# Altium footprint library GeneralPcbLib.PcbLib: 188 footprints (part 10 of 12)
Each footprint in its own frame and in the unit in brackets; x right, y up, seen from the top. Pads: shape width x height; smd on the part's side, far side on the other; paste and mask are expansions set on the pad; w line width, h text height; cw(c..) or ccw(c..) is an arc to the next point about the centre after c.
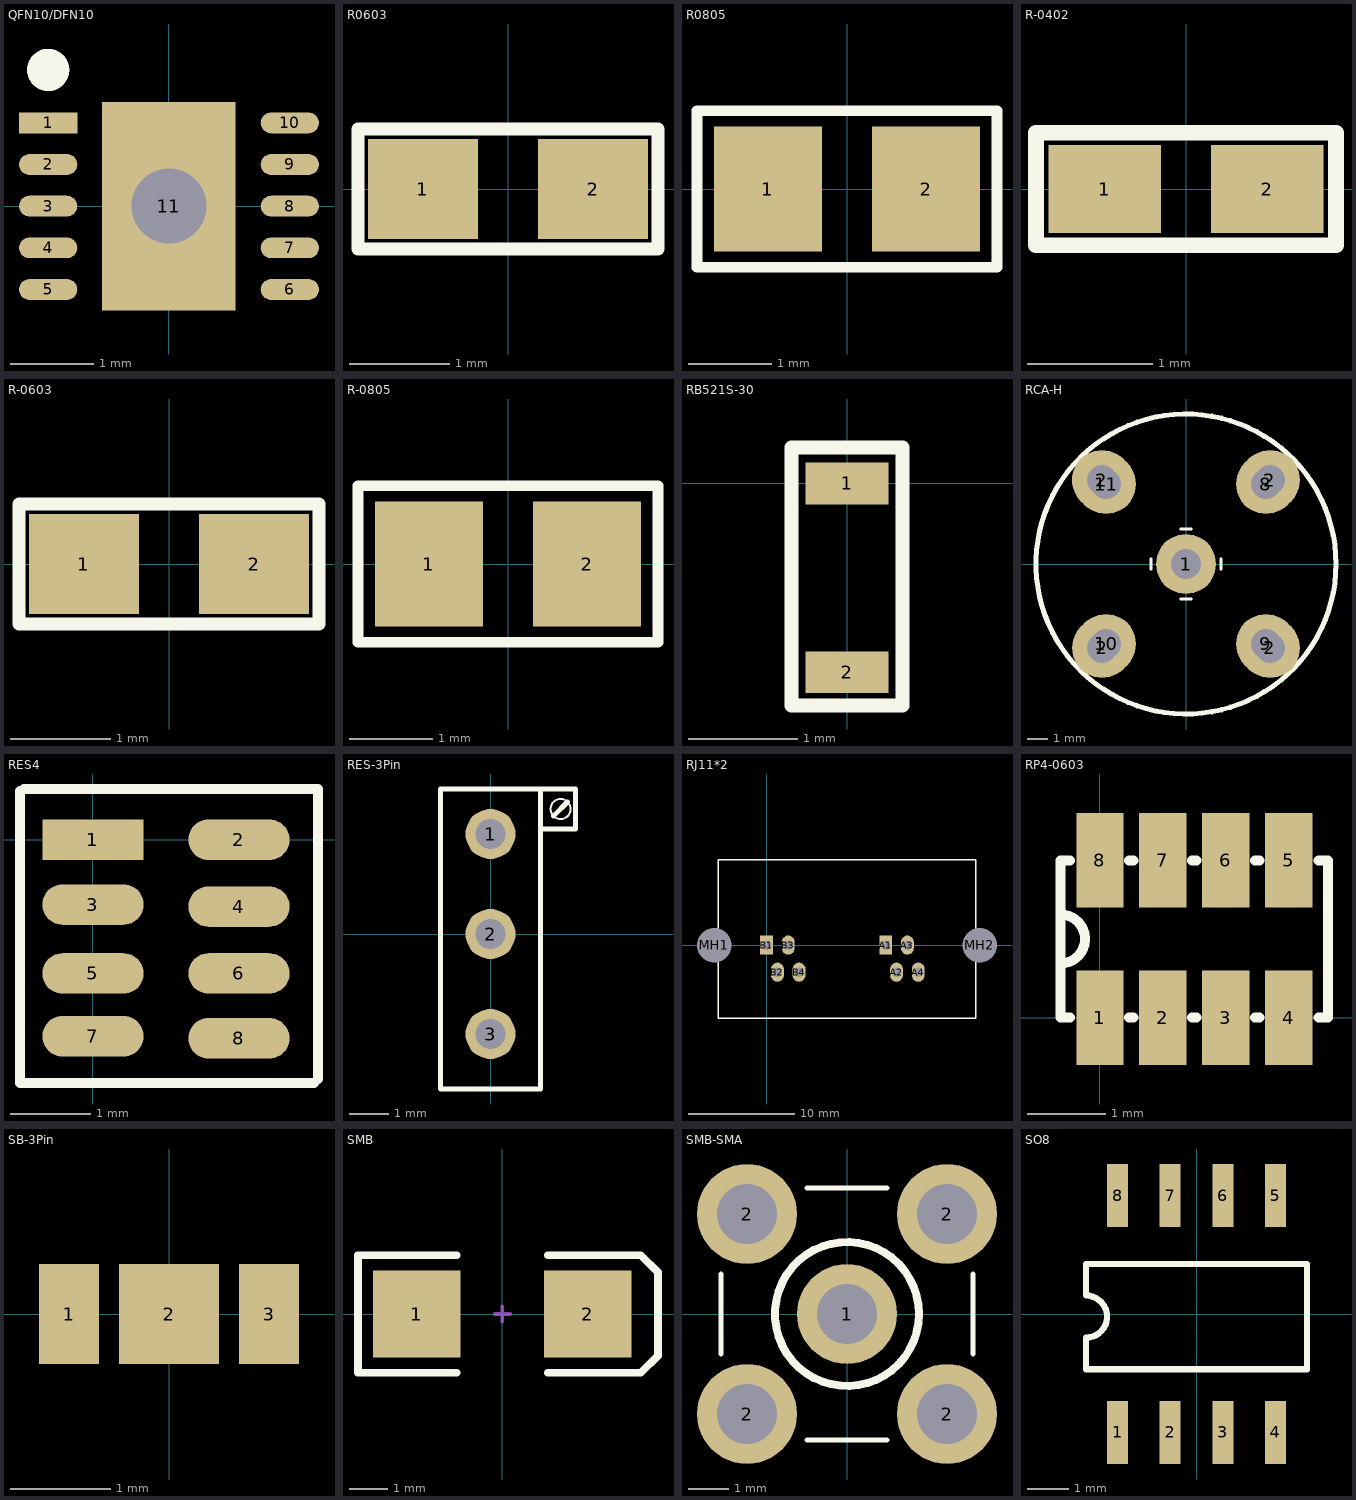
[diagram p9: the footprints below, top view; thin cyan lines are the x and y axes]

## QFN10/DFN10 [mm] "LT3471"
pads (11):
  rect 0.7x0.25 smd: 1(-1.448,1)
  oval 0.7x0.25 smd: 2(-1.448,0.5) 3(-1.448,0) 4(-1.448,-0.5) 5(-1.448,-1) 6(1.452,-1) 7(1.452,-0.5) 8(1.452,0) 9(1.452,0.5) 10(1.452,1)
  rect 1.6x2.5 hole 0.9: 11(0,0)
Top Overlay:
  circle w0.254: c-1.448,1.635 r0.127

## R0603 [mm]
pads (2):
  rect 1.1x1 smd: 1(-0.85,0) 2(0.85,0)
Top Overlay:
  lines w0.127: -1.5,-0.6 1.5,-0.6 1.5,0.6 -1.5,0.6 -1.5,-0.6

## R0805 [mm]
pads (2):
  rect 1.3x1.5 smd: 1(-0.95,0) 2(0.95,0)
Top Overlay:
  lines w0.127: -1.803,-0.94 -1.803,0.94 1.803,0.94 1.803,-0.94 -1.803,-0.94

## R-0402 [mm]
pads (2):
  rect 0.9x0.7 smd: 1(-0.65,0) 2(0.65,0)
Top Overlay:
  lines w0.127: -1.2,-0.45 -1.2,0.45 1.2,0.45 1.2,-0.45 -1.2,-0.45
3D body: height 0.3, standoff 0, extent 0.508,-0.254 1.016,0.254
3D body: height 0.3, standoff 0, extent -1.016,-0.254 -0.508,0.254

## R-0603 [mm]
height 0.5
pads (2):
  rect 1.1x1 smd: 1(-0.85,0) 2(0.85,0)
Top Overlay:
  lines w0.127: -1.5,-0.6 1.5,-0.6 1.5,0.6 -1.5,0.6 -1.5,-0.6
3D body: height 0.5, standoff 0, extent -1.35,-0.45 1.35,0.45

## R-0805 [mm]
pads (2):
  rect 1.3x1.5 smd: 1(-0.95,0) 2(0.95,0)
Top Overlay:
  lines w0.127: -1.803,-0.94 1.803,-0.94 1.803,0.94 -1.803,0.94 -1.803,-0.94

## RB521S-30 [mil]
pads (3):
  round 10 on Top Overlay: 0(-15,20)
  rect 30x15 smd: 1(0,0) 2(0,-68)
Top Overlay:
  lines w5: -20,-80 -20,13 20,13 20,-80 -20,-80

## RCA-H [mm] "立式RCA"
pads (9):
  round 3 hole 1.5: 1(0,0) 2(-4.2,4.2) 2(-4.2,-4.2) 2(4.2,-4.2) 2(4.2,4.2) 8(4,4) 9(4,-4) 10(-4,-4) 11(-4,4)
Top Overlay:
  circle w0.254: c0,0 r7.5
  lines w0.127: -1.75,-0.27 -1.75,0.27 ; -0.27,-1.75 0.27,-1.75 ; -0.27,1.75 0.27,1.75 ; 1.75,-0.27 1.75,0.27

## RES4 [mil] "RES4-0603"
pads (8):
  rect 50x20 smd: 1(0,0)
  oval 50x20 smd: 2(72,0) 3(0,-32) 4(72,-33) 5(0,-66) 6(72,-66) 7(0,-97) 8(72,-98)
Top Overlay:
  lines w5: -36,24 -36,-96 -36,-105.62 -36,-120 109,-120 ; -34,25 111,25 111,12.38 111,-107.62 111,-118

## RES-3Pin [mil] "可调电位器"
height 393.7
pads (3):
  round 50 hole 30: 1(0,100) 2(0,0) 3(0,-100)
Top Overlay:
  circle w2: c70,125 r10
  lines w5: 50,105 85,105 85,145 50,145 ; 63.16,118.16 77,132 ; 50,145 50,-155 -50,-155 -50,145 50,145

## RJ11*2 [mm] "2位RJ11接口座"
height 10
pads (10):
  rect 1.2x1.8 hole 0.9: A1(11.176,0) B1(0,0)
  oval 1.2x1.8 hole 0.9: A2(12.192,-2.54) A3(13.208,0) A4(14.224,-2.54) B2(1.016,-2.54) B3(2.032,0) B4(3.048,-2.54)
  round 2.95 hole 3.25 unplated: MH1(-4.902,0) MH2(19.99,0)
Top Overlay:
  lines w0.127: -4.521,-6.858 -4.521,8.001 19.609,8.001 19.609,-6.858 -4.521,-6.858

## RP4-0603 [mm]
pads (8):
  rect 0.6x1.2 smd: 1(0,0) 2(0.8,0) 3(1.6,0) 4(2.4,0) 5(2.4,2) 6(1.6,2) 7(0.8,2) 8(0,2)
Top Overlay:
  lines w0.127: -0.5,0.689 ccw(c-0.5,1) -0.5,1.312 ; -0.38,0 -0.5,0 -0.5,2 -0.38,2 ; 0.37,0 0.43,0 ; 0.37,2 0.43,2 ; 1.17,0 1.23,0 ; 1.17,2 1.23,2 ; 1.97,0 2.03,0 ; 1.97,2 2.03,2 ; 2.78,0 2.9,0 2.9,2 2.78,2

## SB-3Pin [mm] "3Pin"
pads (3):
  rect 0.6x1 smd: 1(-1,0) 3(1,0)
  rect 1x1 smd: 2(0,0)

## SMB [mm] "DO-214-AA/SMB; 2 C-Bend Leads; Body 5.3 x 3.6 mm, inc. leads (LxW)"
height 2.54
pads (2):
  rect 2.3x2.3 smd: 1(-2.25,0) 2(2.25,0)
Top Overlay:
  lines w0.2: -1.2,-1.55 -3.8,-1.55 -3.8,1.55 -1.2,1.55 ; 1.2,-1.55 3.65,-1.55 4.1,-1.1 4.1,1.1 3.65,1.55 1.2,1.55
Mechanical 1:
  lines w0.1: -0.2,0 0.2,0 ; 0,-0.2 0,0.2

## SMB-SMA [mm]
height 10
pads (5):
  round 2.5 hole 1.5: 1(0,0) 2(-2.5,-2.5) 2(-2.5,2.5) 2(2.5,-2.5) 2(2.5,2.5)
Top Overlay:
  circle w0.2: c0,0 r1.8
  lines w0.127: -3.15,-1 -3.15,1 ; -1,-3.15 1,-3.15 ; -1,3.15 1,3.15 ; 3.15,-1 3.15,1
Mechanical 1:
  circle w0.025: c0,0 r1.05
  circle w0.025: c0,0 r0.2

## SO8 [mil]
height 452.76
pads (8):
  rect 20x60 smd: 1(-75,-112.5) 2(-25,-112.5) 3(25,-112.5) 4(75,-112.5) 5(75,112.5) 6(25,112.5) 7(-25,112.5) 8(-75,112.5)
Top Overlay:
  lines w6: -105,-52.5 -105,-22.5 ccw(c-105,-2.5) -105,17.5 -105,47.5 75,47.5 105,47.5 105,-52.5 75,-52.5 -105,-52.5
